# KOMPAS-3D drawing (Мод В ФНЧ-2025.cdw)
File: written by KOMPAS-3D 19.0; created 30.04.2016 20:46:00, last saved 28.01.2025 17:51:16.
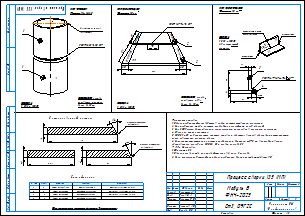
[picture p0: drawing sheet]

Sheet 1: A3, landscape

Document properties: Автор: Владимир; Организация: СПО; Масса: 0; sheetsnumber: 2; Полное имя файла: C:\Users\WELDER_72\OneDrive\Desktop\Мод В ФНЧ-2025.cdw

Title block, sheet 1: Наименование: Модуль В / ФНЧ-2025; designation: Процесс сварки 135 (МП); Материал: Ст3, 09Г2С; Количество листов документа: 1; organisation: Чемпионат ПМ / "Профессионалы"; Форматы листов документа: A3; stored path: C:\Users\Владимир\Desktop\22.cdw; Разработал: Калашников; Проверил: Голов С. А.; Т. контр.: Порошин Г. Ю.; Н. контр.: Красилов А. С.; Утвердил: Дюкова С. В.

Views: Вид 12, Вид 10
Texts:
  Defpoints
  Title Block
  CFS-SHT
  LOGO
  Все размеры на чертеже указаны в миллиметрах
  Технические условия:
  1. Сборка соединений производится в любом пространственном положении;
  2. Все соединения труб и пластин необходимо проклеймить перед сваркой;
  3. Все КСС должны быть сварены с расположением маркировки в указанном положении;
  4. Сварка на спуск запрещена;
  5. КСС В1 - В3 не допускается очистка лицевых и обратных валиков абразивным инструментом
  после завершения процесса сварки.
  6. Выполнить стоп-точки по центру соединения с допуском   37,5 мм в последнем валике
  облицовочного прохода на КСС В2, В3 и первом проходе В3.
  7. XX = Маркировка.
  КСС пластин В3:
  1. Сварка углового шва на лицевой стороне в 2 слоя, 3 прохода;
  2. Угол сопряжения деталей при сборке соединения должен соответствовать 90 .
  КСС ПЛАСТИН В3:
  Tолщина: 10 мм.
  ОЦЕНКА:
  1. ВИК - 100%
  2. Разрушающий
  контроль
  Обратная
  сторона
  Место прихватки
  Место прихватки по центру
  длина, не более 25 мм
  КСС ПЛАСТИН В2:
  Толщина: 10 мм.
  ВНИМАНИЕ: кол-во
  прихваток - две,
  длина до 15 мм.
  № дет.
  Кол-во
  Описание
  Сталь марки 09Г2С
  Труба   114х8-120
  Токарная обработка 30 град.
  Сталь марки Ст3
  Пластина 10х100х250
  Фрезерная обработка 20 град.
  Пластина 10х75х250
  Фрезерная обработка 90 град.
  КСС ТРУБ В1:
  Размер: 114х8-120
  прихваток - четыре,
  длина до 15мм.
  Удерживать на 12 часов
  (не вращать)
  Не оценивается
  ГОСТ 14771-76-Т1- 8
  ГОСТ 16037-80 С17
  ГОСТ 14771-76 С17
  Величина притупления
  на ваш выбор
  Деталировочный чертеж
  CHAIN_RGB_0_0_0_SC_40_THICK_0.18
  CHAIN_RGB_0_0_0_SC_4.7_THICK_0.18
  POLYLINE_STYLE_0.18_RGB_0_0_0
  POLYLINE_STYLE_0.42_RGB_0_0_0
  POLYLINE_STYLE_0.42_RGB_255_0_0
  POLYLINE_STYLE_0.42_RGB_255_255_0
  POLYLINE_STYLE_0.42_RGB_63_0_255
  POLYLINE_STYLE_0.42_RGB_0_127_31
Dimensions and other numbers on the sheet: 40 1; 75; 10; 100; 4; 3; 1; 2; 250; 20; 30 3; 20 2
